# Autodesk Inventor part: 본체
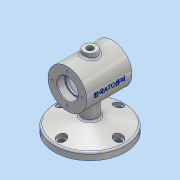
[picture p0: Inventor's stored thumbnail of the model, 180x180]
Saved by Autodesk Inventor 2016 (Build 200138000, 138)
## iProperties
Created: 2018-12
Part Number: 본체
Material: 알루미늄 6061
Document SubType Name: Modeling
Designer: 3sil_cad0123
Density: 2.7 g/cm^3
Appearance: 알루미늄 - 평지
Mass: 685.117 g
Surface Area: 555.89 cm^2
Volume: 253.747 cm^3
Author: 3sil_cad0123
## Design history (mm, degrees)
sketch "스케치1"
  geometry: C1 r 30 at (0, 0); 1 further point
  constraints: 1 centre point, 1 coincident
  dimensions: "d0" = 60 diameter of C1
extrude "돌출1" new body sketch "스케치1" distance "d1" = 70; taper "d2" = 0 deg
node "작업 평면1"
sketch "스케치2"
  geometry: C1 r 25 at (0, 0); 1 further point
  constraints: 1 centre point, 1 coincident
  dimensions: "d3" = 50 diameter of C1
extrude "돌출2" cut sketch "스케치2" stored distance "d4" = 40; taper "d5" = 0 deg
hole "구멍1" diameter "d8" = 28; stored, may be unused: countersink angle "d12" = 90 deg, drill point angle "d14" = 118 deg; dims "d6" = 10, "d7" = 10, "d9" = 6, "d10" = 32, "d11" = 12, "d13" = 8
node "작업 평면2"
sketch "스케치3"
  geometry: C1 r 55 at (0, 35); 1 further point
  constraints: 1 centre point, 1 vertical alignment
  dimensions: "d16" = 110 diameter of C1; "d17" = 35 distance of point (0, 0) C1.centre
extrude "돌출3" join sketch "스케치3" distance "d18" = 11; taper "d19" = 0 deg
sketch "스케치4"
  geometry: C1 r 55 at (0, 0) reference; C2 r 12 at (0, 0); 1 further point
  constraints: 1 centre point, 1 coincident
  dimensions: "d20" = 24 diameter of C2
extrude "돌출4" join sketch "스케치4" stored distance "d21" = 101; taper "d22" = 0 deg
sketch "스케치5"
  geometry: L1 (55, -64)-(55, -75) reference; L2 (55, -75)-(-55, -75) reference; L3 (-55, -75)-(-55, -64) reference; L4 (-55, -64)-(-12, -64) reference; L5 (-12, -64)-(-12, -27.495) reference; L6 (12, -27.495)-(12, -64) reference; L7 (12, -64)-(55, -64) reference; L8 (55, -64)-(-55, -64) reference; L9 (-55, -64)-(4.261, -64); L10 (-55, -64)-(0, -49.263); L11 (-12, -64)-(12, -64) reference; L12 (0, -64)-(0, 0); L13 (-55, -64)-(0, -64); L14 (0, -64)-(55, -64); L15 (0, -49.263)-(55, -64); C1 r 25 at (0, 0) reference; A1 r 30 centre (0, 0) between (12, -27.495) and (-12, -27.495) reference; 1 further point
  constraints: 12 end point, 2 horizontal, 2 point on line, 1 midpoint, 1 vertical
  dimensions: "d96" = 11 distance between parallel lines of L2 L7 (derived); "d97" = 75 deg angle of L1 L15
revolve "회전1" sketch "스케치5" stored, may be unused: angle "d26" = 90 deg
fillet "모깎기1" dims "d27" = 3
node "작업 평면3"
sketch "스케치7"
  geometry: L1 (-30, -35)-(30, -35) reference; C1 r 10 at (0, 0); 1 further point
  constraints: 1 centre point, 1 vertical alignment
  dimensions: "d32" = 20 diameter of C1; "d33" = 35 distance from line of L1 C1.centre
extrude "돌출6" join sketch "스케치7" stored distance "d34" = 40; taper "d35" = 0 deg
fillet "모깎기2" dims "d36" = 3
fillet "모깎기3" dims "d37" = 3
chamfer "모따기1" distance "d38" = 1; stored, may be unused: second distance "d39" = 2, angle "d40" = 45 deg
hole "구멍2" diameter "d43" = 10; stored, may be unused: countersink angle "d47" = 90 deg, drill point angle "d49" = 118 deg; dims "d41" = 10, "d42" = 10, "d44" = 6, "d45" = 32, "d46" = 12, "d48" = 30
fillet "모깎기4" dims "d50" = 3
sketch "스케치8"
  geometry: C1 r 55 at (0, 0) reference; 2 further points
  constraints: 1 horizontal alignment
  dimensions: "d51" = 44 distance of C1.centre point (-44, 0)
hole "구멍3" sketch "스케치8" at (-44, 0) diameter "d52" = 9; stored, may be unused: countersink angle "d56" = 90 deg, drill point angle "d58" = 0 deg; dims "d53" = 6, "d54" = 9, "d55" = 10, "d57" = 10
hole "구멍4" diameter "d61" = 14; stored, may be unused: countersink angle "d65" = 90 deg, drill point angle "d67" = 0 deg; dims "d59" = 10, "d60" = 10, "d62" = 6, "d63" = 9, "d64" = 10, "d66" = 10
sketch "스케치9"
  geometry: C1 r 30 at (0, 0) reference; 1 further point
  constraints: 1 vertical alignment
  dimensions: "d71" = 23 distance of C1.centre point (0, 23)
hole "구멍5" sketch "스케치9" at (0, 23) diameter "d72" = 3.242; stored, may be unused: countersink angle "d76" = 90 deg, drill point angle "d78" = 118 deg; dims "d73" = 8, "d74" = 9, "d75" = 10, "d77" = 10
node "작업 평면6"
sketch "스케치13"
  geometry: L1 (45, 37)-(25, 37) reference; L2 (0, 30)-(70, 30) reference; 2 further points
  constraints: 1 other
  dimensions: "d90" = 35 distance of point (35, 0) point (0, 0); "d92" = 30 distance from line of point (35, 0) L2
feature "엠보싱1" sketch "스케치13" dims "d17" = 35, "d93" = 0.5, "d94" = 0
sketch "스케치14"
  geometry: L1 (-16, -65)-(-13.5, -65) reference; L2 (-13.5, -65)-(-13.5, -75) reference; L3 (-13.5, -75)-(-20, -75) reference; L4 (-20, -75)-(-20, -66.302) reference; L5 (-17.776, -63.404)-(-16, -62.928) reference; L6 (-16, -62.928)-(-16, -65) reference; L7 (83.5, -65)-(86, -65) reference; L8 (86, -65)-(86, -62.928) reference; L9 (86, -62.928)-(87.776, -63.404) reference; L10 (90, -66.302)-(90, -75) reference; L11 (90, -75)-(83.5, -75) reference; L12 (83.5, -75)-(83.5, -65) reference; L13 (70, 17)-(69, 16) reference; L14 (69, 16)-(58, 16) reference; L15 (58, 16)-(58, 14) reference; L16 (58, 14)-(55, 14) reference; L17 (55, 14)-(55, 22) reference; L18 (52, 25)-(40, 25) reference; L19 (40, 25)-(40, 37) reference; L20 (40, 37)-(45, 37) reference; L21 (45, 37)-(45, 33) reference; L22 (48, 30)-(70, 30) reference; L23 (70, 30)-(70, 24.621) reference; L24 (70, 24.621)-(60, 24.621) reference; L25 (60, 24.621)-(59.026, 23) reference; L26 (59.026, 23)-(60, 21.379) reference; L27 (60, 21.379)-(70, 21.379) reference; L28 (70, 21.379)-(70, 17) reference; L29 (15, 22)-(15, 14) reference; L30 (15, 14)-(12, 14) reference; L31 (12, 14)-(12, 16) reference; L32 (12, 16)-(1, 16) reference; L33 (1, 16)-(0, 17) reference; L34 (0, 17)-(0, 21.379) reference; L35 (0, 21.379)-(10, 21.379) reference; L36 (10, 21.379)-(10.974, 23) reference; L37 (10.974, 23)-(10, 24.621) reference; L38 (10, 24.621)-(0, 24.621) reference; L39 (0, 24.621)-(0, 30) reference; L40 (0, 30)-(22, 30) reference; L41 (25, 33)-(25, 37) reference; L42 (25, 37)-(30, 37) reference; L43 (30, 37)-(30, 25) reference; L44 (30, 25)-(18, 25) reference; L45 (18, -25)-(52, -25) reference; L46 (55, -22)-(55, -14) reference; L47 (55, -14)-(58, -14) reference; L48 (58, -14)-(58, -16) reference; L49 (58, -16)-(69, -16) reference; L50 (69, -16)-(70, -17) reference; L51 (70, -17)-(70, -21.379) reference; L52 (70, -21.379)-(60, -21.379) reference; L53 (60, -21.379)-(59.026, -23) reference; L54 (59.026, -23)-(60, -24.621) reference; L55 (60, -24.621)-(70, -24.621) reference; L56 (70, -24.621)-(70, -30) reference; L57 (70, -30)-(50, -30) reference; L58 (47, -33)-(47, -50.176) reference; L59 (49.224, -53.074)-(72, -59.177) reference; L60 (72, -59.177)-(72, -65) reference; L61 (72, -65)-(74.5, -65) reference; L62 (74.5, -65)-(74.5, -75) reference; L63 (74.5, -75)-(-4.5, -75) reference; L64 (-4.5, -75)-(-4.5, -65) reference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; A1 r 3 centre (-17, -66.302) between (-17.776, -63.404) and (-20, -66.302) reference; A2 r 3 centre (87, -66.302) between (90, -66.302) and (87.776, -63.404) reference; A3 r 3 centre (52, 22) between (55, 22) and (52, 25) reference; A4 r 3 centre (18, 22) between (18, 25) and (15, 22) reference; A5 r 3 centre (18, -22) between (15, -22) and (18, -25) reference; A6 r 3 centre (52, -22) between (52, -25) and (55, -22) reference; A7 r 3 centre (50, -50.176) between (47, -50.176) and (49.224, -53.074) reference; A8 r 3 centre (20, -50.176) between (20.776, -53.074) and (23, -50.176) reference; 1 further point
  constraints: 2 end point, 1 vertical, 4 other
  node "절단 모서리 투영2"
fillet "모깎기5" dims "d98" = 0.3
fillet "모깎기6" dims "d99" = 0.3
node "솔리드1"
mirror "대칭1"
pattern_circular "원형 패턴1" dims angle "d69" = 360 deg
pattern_circular "원형 패턴2" dims angle "d80" = 360 deg
mirror "대칭2"
node "절단 모서리 투영1"
other parameters: "d15" = -75, "d31" = -112, "d89" = 30.5
